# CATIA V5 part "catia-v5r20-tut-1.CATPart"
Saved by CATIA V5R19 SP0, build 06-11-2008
Part number: c02tut1
Bounding box of the stored display mesh (mm): x 0 to 0, y 0 to 120, z 0 to 59.981
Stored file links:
  D:\Shriniwas\v5_r19\Part files\c02\c02tut1.CATPart
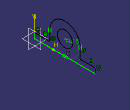
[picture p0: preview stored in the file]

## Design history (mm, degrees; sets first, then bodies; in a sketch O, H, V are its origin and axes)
Body1 (main body)
  Sketch1 on yz-plane, origin (0, 0, 0), H (0, 1, 0), V (0, 0, 1)
    line L1 (0, 0) -> (120, 0)
    line L2 (120, 0) -> (120, 10)
    line L3 (120, 10) -> (90, 10)
    line L4 (90, 10) -> (90, 30)
    arc A1 centre (60, 30) radius 30 from (90, 30) to (30, 30) ccw
    line L5 (30, 30) -> (30, 10)
    point P7 (30, 10)
    line L6 (30, 10) -> (0, 10)
    point P8 (0, 10)
    line L7 (0, 10) -> (0, 0)
    circle A2 centre (60, 30) radius 15
    radius A2 = 15
    horizontal: L1 H, L3 H, L6 H
    vertical: L2 V, L4 V, L7 V
    tangency: A1 L1, A1 L4, L5 A1
    coincidence: P7 L3, P8 V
